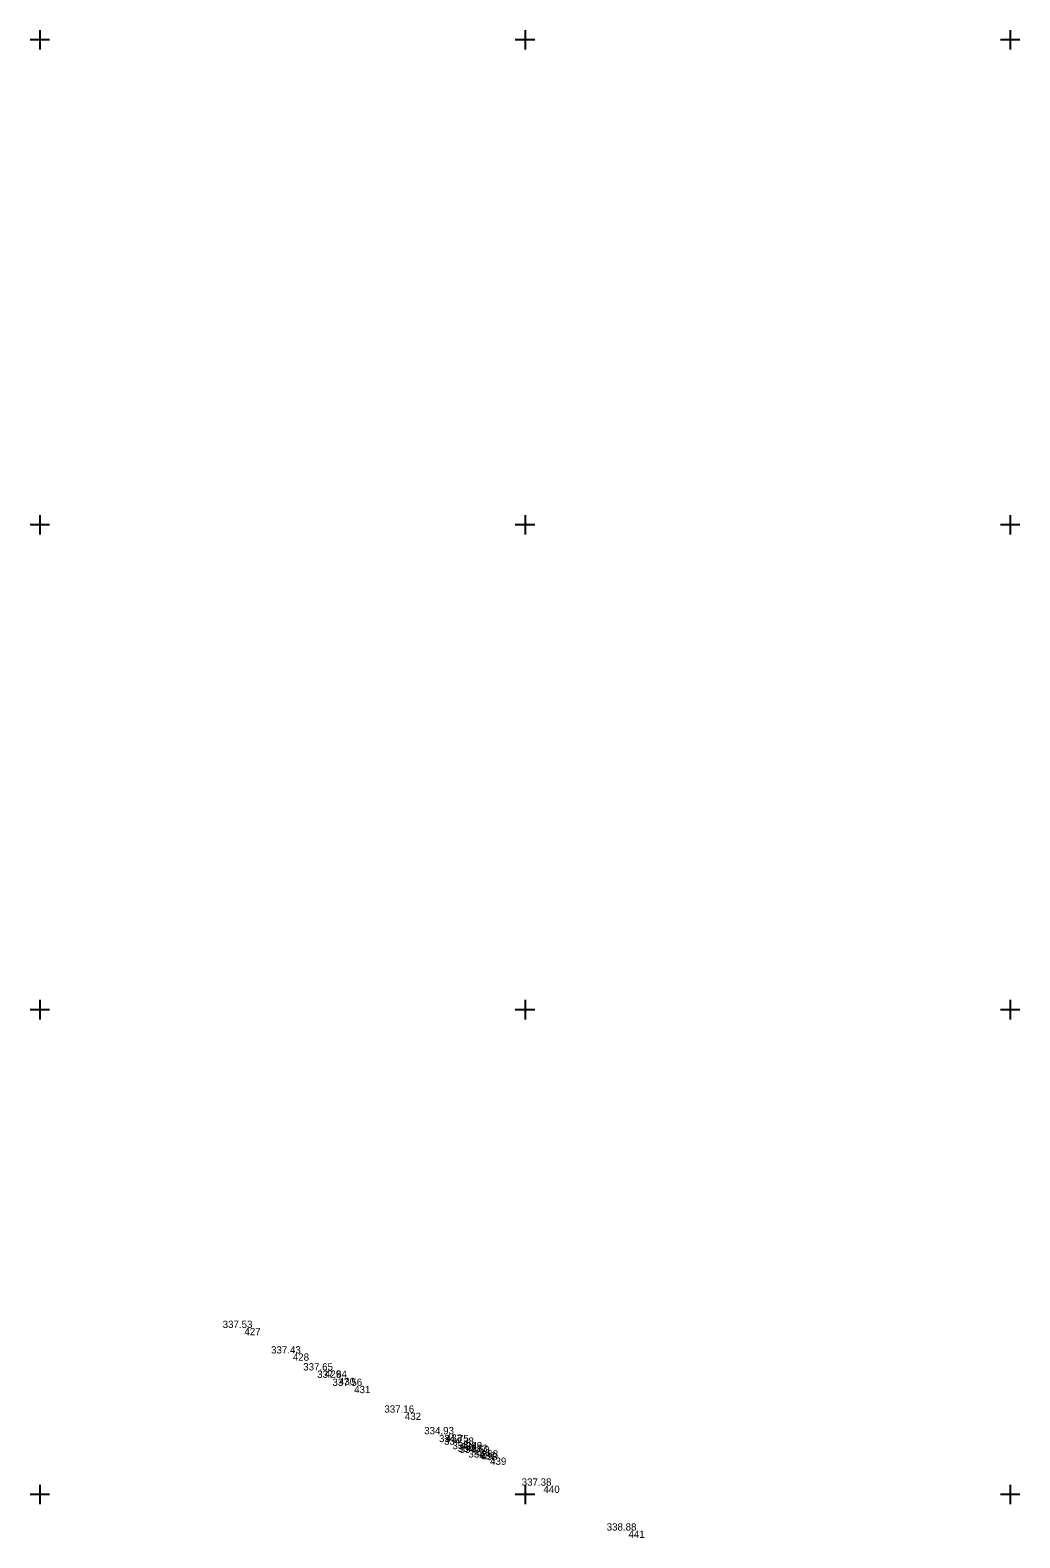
# Model space of a CAD drawing. Extents: x -718951 to -718443, y -1070201 to -1068444.
# Drawn here: x -718701 to -718599, y -1069304.5 to -1069149 of the extents above; entities that cross this region are included whole.
import ezdxf

# ---------------------------------------------------------------- set-up
doc = ezdxf.new("R2010")
doc.units = 0
for name, color, linetype in [('GEO_Body polohopis', 7, 'Continuous'), ('GEO_Hektarová síť', 7, 'Continuous'), ('GEO_Výšky bodů polohopis', 7, 'Continuous'), ('GEO_Čísla bodů polohopis', 7, 'Continuous')]:
    doc.layers.add(name, color=color, linetype=linetype)

msp = doc.modelspace()

# ---------------------------------------------------------------- linework, layer by layer
at = {"layer": 'GEO_Body polohopis'}
for p, q in [((-718678.92, -1069282.82), (-718678.92, -1069282.82)), ((-718673.93, -1069285.45), (-718673.93, -1069285.45)), ((-718670.62, -1069287.2), (-718670.62, -1069287.2)), ((-718669.18, -1069287.96), (-718669.18, -1069287.96)), ((-718667.61, -1069288.79), (-718667.61, -1069288.79)), ((-718662.38, -1069291.55), (-718662.38, -1069291.55)), ((-718658.15, -1069293.78), (-718658.15, -1069293.78)), ((-718656.61, -1069294.59), (-718656.61, -1069294.59)), ((-718656.1, -1069294.86), (-718656.1, -1069294.86)), ((-718655.23, -1069295.32), (-718655.23, -1069295.32)), ((-718654.7, -1069295.6), (-718654.7, -1069295.6)), ((-718654.51, -1069295.7), (-718654.51, -1069295.7)), ((-718653.6, -1069296.18), (-718653.6, -1069296.18)), ((-718648.1, -1069299.08), (-718648.1, -1069299.08)), ((-718639.33, -1069303.71), (-718639.33, -1069303.71))]:
    msp.add_line(p, q, dxfattribs=at)
at = {"layer": 'GEO_Hektarová síť'}
for points in [[(-718700, -1069149), (-718700, -1069150), (-718700, -1069151)], [(-718650, -1069149), (-718650, -1069150), (-718650, -1069151)], [(-718600, -1069149), (-718600, -1069150), (-718600, -1069151)], [(-718699, -1069150), (-718700, -1069150), (-718701, -1069150)], [(-718649, -1069150), (-718650, -1069150), (-718651, -1069150)], [(-718599, -1069150), (-718600, -1069150), (-718601, -1069150)], [(-718700, -1069199), (-718700, -1069200), (-718700, -1069201)], [(-718650, -1069199), (-718650, -1069200), (-718650, -1069201)], [(-718600, -1069199), (-718600, -1069200), (-718600, -1069201)], [(-718699, -1069200), (-718700, -1069200), (-718701, -1069200)], [(-718649, -1069200), (-718650, -1069200), (-718651, -1069200)], [(-718599, -1069200), (-718600, -1069200), (-718601, -1069200)], [(-718700, -1069249), (-718700, -1069250), (-718700, -1069251)], [(-718650, -1069249), (-718650, -1069250), (-718650, -1069251)], [(-718600, -1069249), (-718600, -1069250), (-718600, -1069251)], [(-718699, -1069250), (-718700, -1069250), (-718701, -1069250)], [(-718649, -1069250), (-718650, -1069250), (-718651, -1069250)], [(-718599, -1069250), (-718600, -1069250), (-718601, -1069250)], [(-718699, -1069300), (-718700, -1069300), (-718701, -1069300)], [(-718700, -1069299), (-718700, -1069300), (-718700, -1069301)], [(-718649, -1069300), (-718650, -1069300), (-718651, -1069300)], [(-718650, -1069299), (-718650, -1069300), (-718650, -1069301)], [(-718599, -1069300), (-718600, -1069300), (-718601, -1069300)], [(-718600, -1069299), (-718600, -1069300), (-718600, -1069301)]]:
    msp.add_lwpolyline(points, dxfattribs=at)

# ---------------------------------------------------------------- texts
at = {"layer": 'GEO_Výšky bodů polohopis'}
for s, p in [('337.53 ', (-718681.16, -1069282.82)), ('337.43 ', (-718676.17, -1069285.45)), ('337.65 ', (-718672.86, -1069287.2)), ('337.64 ', (-718671.42, -1069287.96)), ('337.56 ', (-718669.85, -1069288.79)), ('337.16 ', (-718664.49, -1069291.55)), ('334.93 ', (-718660.39, -1069293.78)), ('334.75 ', (-718658.86, -1069294.59)), ('334.38 ', (-718658.34, -1069294.86)), ('334.29 ', (-718657.48, -1069295.32)), ('334.33 ', (-718656.93, -1069295.6)), ('334.60 ', (-718656.75, -1069295.7)), ('334.63 ', (-718655.83, -1069296.18)), ('337.38 ', (-718650.34, -1069299.08)), ('338.88 ', (-718641.58, -1069303.71))]:
    msp.add_text(s, height=0.75, dxfattribs=at).set_placement(p)
at = {"layer": 'GEO_Čísla bodů polohopis'}
for s, p in [('427', (-718678.92, -1069283.57)), ('428', (-718673.93, -1069286.2)), ('429', (-718670.62, -1069287.95)), ('430', (-718669.18, -1069288.71)), ('431', (-718667.61, -1069289.54)), ('432', (-718662.38, -1069292.3)), ('433', (-718658.15, -1069294.53)), ('434', (-718656.61, -1069295.34)), ('435', (-718656.1, -1069295.61)), ('436', (-718655.23, -1069296.07)), ('437', (-718654.7, -1069296.35)), ('438', (-718654.51, -1069296.45)), ('439', (-718653.6, -1069296.93)), ('440', (-718648.1, -1069299.83)), ('441', (-718639.33, -1069304.46))]:
    msp.add_text(s, height=0.75, dxfattribs=at).set_placement(p)

doc.saveas('drawing.dxf')
